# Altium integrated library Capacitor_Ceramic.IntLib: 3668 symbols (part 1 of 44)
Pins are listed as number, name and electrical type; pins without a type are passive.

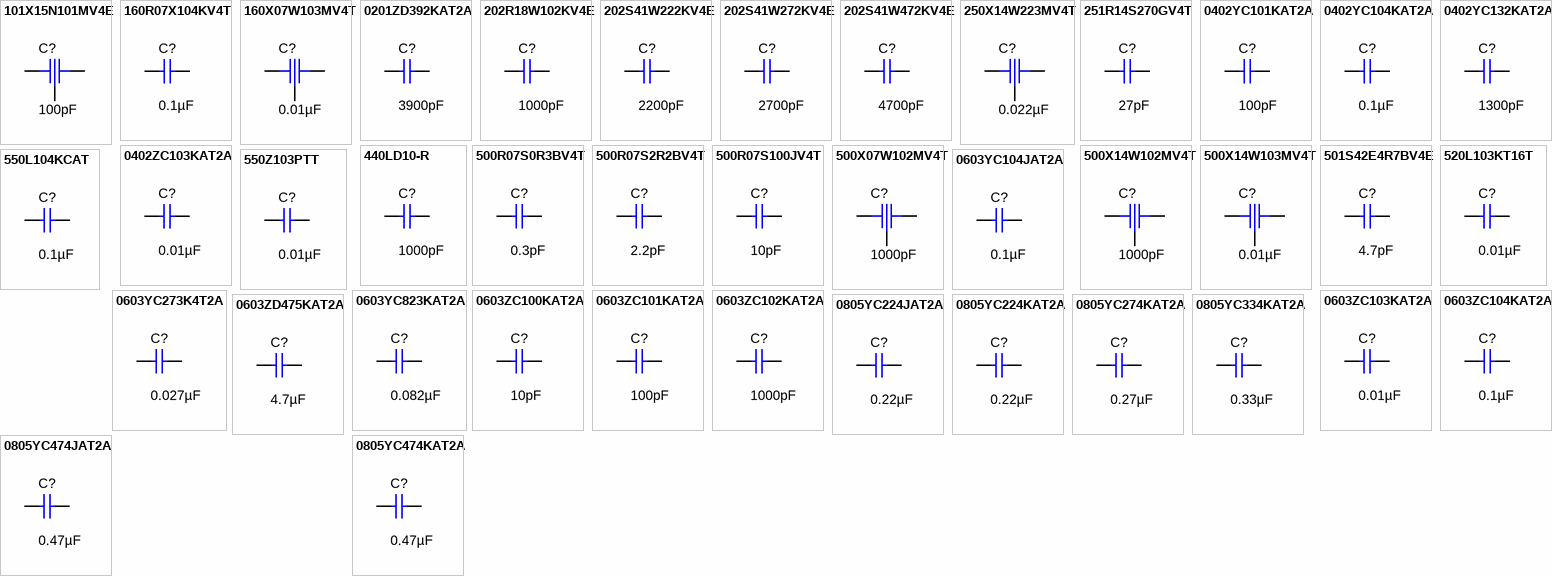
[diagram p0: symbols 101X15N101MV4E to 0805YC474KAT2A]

## 101X15N101MV4E
designator C?  ValueDisplayed: 100pF  (hidden comment: 101X15N101MV4E)
CAP, CERM, 100 pF, 100 V,+/- 20%, C0G/NP0, 0805; Manufacturer: Johanson Technology; SymbolCreator: a0411947; CompType: Capacitor; U/M: EA; Cap_F: 0.0000000001; Value: 100pF; Tolerance_%: 20; VDC_V: 100; Value2: 100V; TaMin_C: -55; TaMax_C: 125; Polarized: N; Cap_Case: 0805; SizeArea_mm2: 2.58064; SizeAreaWB_mm2: 6.88264; SizeX_mm: 2.032; SizeY_mm: 1.27; SizeZ_mm: 1.016; AEC Category: Q200; Green_Lifecycle: Not Set; Green_REACh: Incomplete
footprint X2Y_0805
pins: 1, 2, 3

## 160R07X104KV4T
designator C?  ValueDisplayed: 0.1µF  (hidden comment: 160R07X104KV4T)
CAP, CERM, 0.1 µF, 16 V,+/- 10%, X5R, 0402; Manufacturer: Johanson Technology; Polarized: N; CompType: Capacitor; Value: 0.1uF; U/M: EA; Cap_F: 0.0000001; Tolerance_%: 10; VDC_V: 16; Value2: 16V; TaMin_C: -55; TaMax_C: 85; Cap_Case: 0402; SizeArea_mm2: 0.5; SizeAreaWB_mm2: 3; SizeX_mm: 1; SizeZ_mm: 0.65; AEC Category: Q200; Green_Lifecycle: Not Set; Green_REACh: Incomplete
signal-integrity model Cap
simulation model Cap
footprint 0402_065
footprint 0402_065M
footprint 0402_065L
footprint 0402_065S
pins: 1, 2

## 160X07W103MV4T
designator C?  ValueDisplayed: 0.01µF  (hidden comment: 160X07W103MV4T)
CAP, CERM, 0.01 µF, 16 V,+/- 20%, X7R, 0402; Manufacturer: Johanson Technology; SymbolCreator: a0411947; CompType: Capacitor; U/M: EA; Cap_F: 0.00000001; Value: 0.01uF; Tolerance_%: 20; VDC_V: 16; Value2: 16V; TaMin_C: -55; TaMax_C: 125; Polarized: N; Cap_Case: 0402; SizeArea_mm2: 0.7296; SizeAreaWB_mm2: 3.5096; SizeX_mm: 1.14; SizeY_mm: 0.64; SizeZ_mm: 0.51; AEC Category: Q200
footprint X2Y_0402
pins: 1, 2, 3

## 0201ZD392KAT2A
designator C?  ValueDisplayed: 3900pF  (hidden comment: 0201ZD392KAT2A)
CAP, CERM, 3900 pF, 10 V,+/- 10%, X5R, 0201; Manufacturer: AVX; Polarized: N; CompType: Capacitor; Value: 3900pF; U/M: EA; Cap_F: 0.0000000039; Tolerance_%: 10; Value2: 10V; TaMin_C: -55; TaMax_C: 85; Cap_Case: 0201; SizeArea_mm2: 0.18; SizeAreaWB_mm2: 2.08; SizeX_mm: 0.6; SizeY_mm: 0.3; SizeZ_mm: 0.26; AEC Category: Q200; Green_Lifecycle: Active; Green_REACh: Passed
signal-integrity model Cap
simulation model Cap
footprint 0201
footprint 0201M
footprint 0201L
footprint 0201_Silk
pins: 1, 2

## 202R18W102KV4E
designator C?  ValueDisplayed: 1000pF  (hidden comment: 202R18W102KV4E)
CAP, CERM, 1000 pF, 2000 V,+/- 10%, X7R, 1206; Manufacturer: Johanson Technology; Polarized: N; CompType: Capacitor; Value: 1000pF; U/M: EA; Cap_F: 0.000000001; Tolerance_%: 10; VDC_V: 2000; Value2: 2000V; TaMin_C: -55; TaMax_C: 125; Cap_Case: 1206; SizeArea_mm2: 5.12; SizeAreaWB_mm2: 10.92; SizeX_mm: 3.2; SizeY_mm: 1.6; SizeZ_mm: 1.9; AEC Category: Q200
signal-integrity model Cap
simulation model Cap
footprint 1206_190
footprint 1206_190M
footprint 1206_190L
pins: 1, 2

## 202S41W222KV4E
designator C?  ValueDisplayed: 2200pF  (hidden comment: 202S41W222KV4E)
CAP, CERM, 2200 pF, 2000 V,+/- 10%, X7R, 1210; Manufacturer: Johanson Technology; Polarized: N; CompType: Capacitor; Value: 2200pF; U/M: EA; Cap_F: 0.0000000022; Tolerance_%: 10; VDC_V: 2000; Value2: 2000V; TaMin_C: -55; TaMax_C: 125; Cap_Case: 1210; SizeArea_mm2: 8; SizeAreaWB_mm2: 14.7; SizeX_mm: 3.2; SizeY_mm: 2.5; SizeZ_mm: 2.8; AEC Category: Q200
signal-integrity model Cap
simulation model Cap
footprint 1210_280
pins: 1, 2

## 202S41W272KV4E
designator C?  ValueDisplayed: 2700pF  (hidden comment: 202S41W272KV4E)
CAP, CERM, 2700 pF, 2000 V,+/- 10%, X7R, 1210; Manufacturer: Johanson Technology; Polarized: N; CompType: Capacitor; Value: 2700pF; U/M: EA; Cap_F: 0.0000000027; Tolerance_%: 10; VDC_V: 2000; Value2: 2000V; TaMin_C: -55; TaMax_C: 125; Cap_Case: 1210; SizeArea_mm2: 8; SizeAreaWB_mm2: 14.7; SizeX_mm: 3.2; SizeY_mm: 2.5; SizeZ_mm: 2.8; AEC Category: Q200
signal-integrity model Cap
simulation model Cap
footprint 1210_280
pins: 1, 2

## 202S41W472KV4E
designator C?  ValueDisplayed: 4700pF  (hidden comment: 202S41W472KV4E)
CAP, CERM, 4700 pF, 2000 V,+/- 10%, X7R, 1210; Manufacturer: Johanson Technology; Polarized: N; CompType: Capacitor; Value: 4700pF; U/M: EA; Cap_F: 0.0000000047; Tolerance_%: 10; VDC_V: 2000; Value2: 2000V; TaMin_C: -55; TaMax_C: 125; Cap_Case: 1210; SizeArea_mm2: 8; SizeAreaWB_mm2: 14.7; SizeX_mm: 3.2; SizeY_mm: 2.5; SizeZ_mm: 1.35; AEC Category: Q200; Green_Lifecycle: Not Set; Green_REACh: Incomplete
signal-integrity model Cap
simulation model Cap
footprint 1210
footprint 1210M
footprint 1210L
pins: 1, 2

## 250X14W223MV4T
designator C?  ValueDisplayed: 0.022µF  (hidden comment: 250X14W223MV4T)
CAP, CERM, 0.022 µF, 25 V,+/- 20%, X7R, 0603; Manufacturer: Johanson Technology; SymbolCreator: a0411947; CompType: Capacitor; U/M: EA; Cap_F: 0.000000022; Value: 0.022uF; Tolerance_%: 20; VDC_V: 25; Value2: 25V; TaMin_C: -55; TaMax_C: 125; Polarized: N; Cap_Case: 0603; SizeArea_mm2: 1.445514; SizeAreaWB_mm2: 4.960514; SizeX_mm: 1.626; SizeY_mm: 0.889; SizeZ_mm: 0.66; AEC Category: Q200; Green_Lifecycle: Active; Green_REACh: Passed
footprint X2Y_0603
pins: 1, 2, 3

## 251R14S270GV4T
designator C?  ValueDisplayed: 27pF  (hidden comment: 251R14S270GV4T)
CAP, CERM, 27 pF, 250 V,+/- 2%, C0G/NP0, 0603; Manufacturer: Johanson Technology; Polarized: N; CompType: Capacitor; Value: 27pF; U/M: EA; Cap_F: 0.000000000027; Tolerance_%: 2; VDC_V: 250; Value2: 250V; TaMin_C: -55; TaMax_C: 125; Cap_Case: 0603; SizeArea_mm2: 1.28; SizeAreaWB_mm2: 4.68; SizeX_mm: 1.6; SizeY_mm: 0.8; SizeZ_mm: 1; AEC Category: Q200
signal-integrity model Cap
simulation model Cap
footprint 0603
footprint 0603M
footprint 0603L
footprint 0603_HV
footprint 0603S
pins: 1, 2

## 0402YC101KAT2A
designator C?  ValueDisplayed: 100pF  (hidden comment: 0402YC101KAT2A)
CAP, CERM, 100 pF, 16 V,+/- 10%, X7R, 0402; Manufacturer: AVX; Polarized: N; CompType: Capacitor; Value: 100pF; U/M: EA; Cap_F: 0.0000000001; Tolerance_%: 10; VDC_V: 16; Value2: 16V; TaMin_C: -55; TaMax_C: 125; Cap_Case: 0402; SizeArea_mm2: 0.5; SizeAreaWB_mm2: 3; SizeX_mm: 1; SizeZ_mm: 0.6; AEC Category: Q200
signal-integrity model Cap
simulation model Cap
footprint 0402
footprint 0402M
footprint 0402L
footprint 0402S
pins: 1, 2

## 0402YC104KAT2A
designator C?  ValueDisplayed: 0.1µF  (hidden comment: 0402YC104KAT2A)
CAP, CERM, 0.1 µF, 16 V,+/- 10%, X7R, 0402; Manufacturer: AVX; Polarized: N; CompType: Capacitor; Value: 0.1uF; U/M: EA; Cap_F: 0.0000001; Tolerance_%: 10; VDC_V: 16; Value2: 16V; TaMin_C: -55; TaMax_C: 125; Cap_Case: 0402; SizeArea_mm2: 0.5; SizeAreaWB_mm2: 3; SizeX_mm: 1; SizeZ_mm: 0.6; AEC Category: Q200; Green_Lifecycle: Active; Green_REACh: Passed
signal-integrity model Cap
simulation model Cap
footprint 0402
footprint 0402M
footprint 0402L
footprint 0402S
pins: 1, 2

## 0402YC132KAT2A
designator C?  ValueDisplayed: 1300pF  (hidden comment: 0402YC132KAT2A)
CAP, CERM, 1300 pF, 16 V,+/- 10%, X7R, 0402; Manufacturer: AVX; Polarized: N; CompType: Capacitor; Value: 1300pF; U/M: EA; Cap_F: 0.0000000013; Tolerance_%: 10; VDC_V: 16; Value2: 16V; TaMin_C: -55; TaMax_C: 125; Cap_Case: 0402; SizeArea_mm2: 0.5; SizeAreaWB_mm2: 3; SizeX_mm: 1; SizeZ_mm: 0.6; AEC Category: Q200; Green_Lifecycle: Not Set; Green_REACh: Incomplete
signal-integrity model Cap
simulation model Cap
footprint 0402
footprint 0402M
footprint 0402L
footprint 0402S
pins: 1, 2

## 0402ZC103KAT2A
designator C?  ValueDisplayed: 0.01µF  (hidden comment: 0402ZC103KAT2A)
CAP, CERM, 0.01 µF, 10 V,+/- 10%, X7R, 0402; Manufacturer: AVX; Polarized: N; CompType: Capacitor; Value: 0.01uF; U/M: EA; Cap_F: 0.00000001; Tolerance_%: 10; Value2: 10V; TaMin_C: -55; TaMax_C: 125; Cap_Case: 0402; SizeArea_mm2: 0.5; SizeAreaWB_mm2: 3; SizeX_mm: 1; SizeZ_mm: 0.6; AEC Category: Q200
signal-integrity model Cap
simulation model Cap
footprint 0402
footprint 0402M
footprint 0402L
footprint 0402S
pins: 1, 2

## 440LD10-R
designator C?  ValueDisplayed: 1000pF  (hidden comment: 440LD10-R)
CAP, CERM, 1000 pF, X1 760 VAC/Y1 500 VAC, +/- 20%, Y5U, Disc, 9.3x12.5mm; Manufacturer: Yageo America; Polarized: N; CompType: Capacitor; Value: 1000pF; U/M: EA; Cap_F: 0.000000001; Tolerance_%: 20; TaMin_C: -30; TaMax_C: 125; Cap_Case: 440L_930x1250; SizeArea_mm2: 53.01; SizeAreaWB_mm2: 87.01; SizeX_mm: 9.3; SizeY_mm: 5.7; SizeZ_mm: 12.5; AEC Category: Q200; Green_Lifecycle: Active; Green_REACh: Passed; AC_Safety: X1Y1; VAC_X: 760; VAC_Y: 500
signal-integrity model Cap
simulation model Cap
footprint 440L_930x1250
pins: 1, 2

## 500R07S0R3BV4T
designator C?  ValueDisplayed: 0.3pF  (hidden comment: 500R07S0R3BV4T)
CAP, CERM, 0.3 pF, 50 V,+/- 30%, C0G/NP0, 0402; Manufacturer: Johanson Technology; Polarized: N; CompType: Capacitor; Value: 0.3pF; U/M: EA; Cap_F: 0.0000000000003; Tolerance_%: 30; VDC_V: 50; Value2: 50V; TaMin_C: -55; TaMax_C: 125; Cap_Case: 0402; SizeArea_mm2: 0.5; SizeAreaWB_mm2: 3; SizeX_mm: 1; SizeZ_mm: 0.6; AEC Category: Q200
signal-integrity model Cap
simulation model Cap
footprint 0402
footprint 0402M
footprint 0402L
footprint 0402S
pins: 1, 2

## 500R07S2R2BV4T
designator C?  ValueDisplayed: 2.2pF  (hidden comment: 500R07S2R2BV4T)
CAP, CERM, 2.2 pF, 50 V,+/- 5%, C0G/NP0, 0402; Manufacturer: Johanson Technology; Polarized: N; CompType: Capacitor; Value: 2.2pF; U/M: EA; Cap_F: 0.0000000000022; Tolerance_%: 5; VDC_V: 50; Value2: 50V; TaMin_C: -55; TaMax_C: 125; Cap_Case: 0402; SizeArea_mm2: 0.5; SizeAreaWB_mm2: 3; SizeX_mm: 1; SizeZ_mm: 0.6; AEC Category: Q200
signal-integrity model Cap
simulation model Cap
footprint 0402
footprint 0402M
footprint 0402L
footprint 0402S
pins: 1, 2

## 500R07S100JV4T
designator C?  ValueDisplayed: 10pF  (hidden comment: 500R07S100JV4T)
CAP, CERM, 10 pF, 50 V,+/- 5%, C0G/NP0, 0402; Manufacturer: Johanson Technology; Polarized: N; CompType: Capacitor; Value: 10pF; U/M: EA; Cap_F: 0.00000000001; Tolerance_%: 5; VDC_V: 50; Value2: 50V; TaMin_C: -55; TaMax_C: 125; Cap_Case: 0402; SizeArea_mm2: 0.5; SizeAreaWB_mm2: 3; SizeX_mm: 1; SizeZ_mm: 0.6; AEC Category: Q200; Green_Lifecycle: Active; Green_REACh: Passed
signal-integrity model Cap
simulation model Cap
footprint 0402
footprint 0402M
footprint 0402L
footprint 0402S
pins: 1, 2

## 500X07W102MV4T
designator C?  ValueDisplayed: 1000pF  (hidden comment: 500X07W102MV4T)
CAP, CERM, 1000 pF, 50 V,+/- 20%, X7R, 0402; Manufacturer: Johanson Technology; SymbolCreator: a0411947; CompType: Capacitor; U/M: EA; Cap_F: 0.000000001; Value: 1000pF; Tolerance_%: 20; VDC_V: 50; Value2: 50V; TaMin_C: -55; TaMax_C: 125; Polarized: N; Cap_Case: 0402; SizeArea_mm2: 0.7296; SizeAreaWB_mm2: 3.5096; SizeX_mm: 1.14; SizeY_mm: 0.64; SizeZ_mm: 0.51; AEC Category: Q200
footprint X2Y_0402
pins: 1, 2, 3

## 500X14W102MV4T
designator C?  ValueDisplayed: 1000pF  (hidden comment: 500X14W102MV4T)
CAP, CERM, 1000 pF, 50 V,+/- 20%, X7R, 0603; Manufacturer: Johanson Technology; SymbolCreator: a0411947; CompType: Capacitor; U/M: EA; Cap_F: 0.000000001; Value: 1000pF; Tolerance_%: 20; VDC_V: 50; Value2: 50V; TaMin_C: -55; TaMax_C: 125; Polarized: N; Cap_Case: 0603; SizeArea_mm2: 1.445514; SizeAreaWB_mm2: 4.960514; SizeX_mm: 1.626; SizeY_mm: 0.889; SizeZ_mm: 0.66; AEC Category: Q200
footprint X2Y_0603
pins: 1, 2, 3

## 500X14W103MV4T
designator C?  ValueDisplayed: 0.01µF  (hidden comment: 500X14W103MV4T)
CAP, CERM, 0.01 µF, 50 V,+/- 20%, X7R, 0603; Manufacturer: Johanson Technology; SymbolCreator: a0411947; CompType: Capacitor; U/M: EA; Cap_F: 0.00000001; Value: 0.01uF; Tolerance_%: 20; VDC_V: 50; Value2: 50V; TaMin_C: -55; TaMax_C: 125; Polarized: N; Cap_Case: 0603; SizeArea_mm2: 1.445514; SizeAreaWB_mm2: 4.960514; SizeX_mm: 1.626; SizeY_mm: 0.889; SizeZ_mm: 0.66; AEC Category: Q200
footprint X2Y_0603
pins: 1, 2, 3

## 501S42E4R7BV4E
designator C?  ValueDisplayed: 4.7pF  (hidden comment: 501S42E4R7BV4E)
CAP, CERM, 4.7 pF, 500 V,+/- 2%, C0G/NP0, 1111; Manufacturer: Johanson Technology; Polarized: N; CompType: Capacitor; Value: 4.7pF; U/M: EA; Cap_F: 0.0000000000047; Tolerance_%: 2; VDC_V: 500; Value2: 500V; TaMin_C: -55; TaMax_C: 125; Cap_Case: 1111; SizeArea_mm2: 7.7841; SizeAreaWB_mm2: 14.3641; SizeX_mm: 2.79; SizeZ_mm: 2.59; AEC Category: Q200
signal-integrity model Cap
simulation model Cap
footprint 1111
footprint 1111M
footprint 1111L
pins: 1, 2

## 520L103KT16T
designator C?  ValueDisplayed: 0.01µF  (hidden comment: 520L103KT16T)
CAP, CERM, 0.01 µF, 16 V,+/- 10%, X7R, 0402; Manufacturer: AT Ceramics; Polarized: N; CompType: Capacitor; Value: 0.01uF; U/M: EA; Cap_F: 0.00000001; Tolerance_%: 10; VDC_V: 16; Value2: 16V; TaMin_C: -55; TaMax_C: 125; Cap_Case: 0402; SizeArea_mm2: 0.5; SizeAreaWB_mm2: 3; SizeX_mm: 1; SizeZ_mm: 0.65; AEC Category: Q200; Green_Lifecycle: Not Set; Green_REACh: Incomplete
signal-integrity model Cap
simulation model Cap
footprint 0402_065
footprint 0402_065M
footprint 0402_065L
footprint 0402_065S
pins: 1, 2

## 550L104KCAT
designator C?  ValueDisplayed: 0.1µF  (hidden comment: 550L104KCAT)
CAP, CERM, 0.1 µF, 16 V,+/- 10%, 0402; Manufacturer: AT Ceramics; Polarized: N; CompType: Capacitor; Value: 0.1uF; U/M: EA; Cap_F: 0.0000001; Tolerance_%: 10; VDC_V: 16; Value2: 16V; TempCo: Unknown; TaMin_C: -55; TaMax_C: 125; Cap_Case: 0402; SizeArea_mm2: 0.5; SizeAreaWB_mm2: 3; SizeX_mm: 1; SizeZ_mm: 0.65; AEC Category: Q200; Green_Lifecycle: Not Set; Green_REACh: Incomplete
signal-integrity model Cap
simulation model Cap
footprint 0402_065
footprint 0402_065M
footprint 0402_065L
footprint 0402_065S
pins: 1, 2

## 550Z103PTT
designator C?  ValueDisplayed: 0.01µF  (hidden comment: 550Z103PTT)
CAP, CERM, 0.01 µF, 6.3 V,+100/-0%, C0G/NP0, 0201; Manufacturer: AT Ceramics; Polarized: N; CompType: Capacitor; Value: 0.01uF; U/M: EA; Cap_F: 0.00000001; Tolerance_%: 100; VDC_V: 6.3; Value2: 6.3V; TaMin_C: -55; TaMax_C: 125; Cap_Case: 0201; SizeArea_mm2: 0.18; SizeAreaWB_mm2: 2.08; SizeX_mm: 0.6; SizeY_mm: 0.3; SizeZ_mm: 0.33; AEC Category: Q200; Green_Lifecycle: Not Set; Green_REACh: Incomplete
signal-integrity model Cap
simulation model Cap
footprint 0201_033
footprint 0201_033M
footprint 0201_033L
pins: 1, 2

## 0603YC104JAT2A
designator C?  ValueDisplayed: 0.1µF  (hidden comment: 0603YC104JAT2A)
CAP, CERM, 0.1 µF, 16 V,+/- 5%, X7R, 0603; Manufacturer: AVX; Polarized: N; CompType: Capacitor; Value: 0.1uF; U/M: EA; Cap_F: 0.0000001; Tolerance_%: 5; ESR_ohm: 0.039; Value1: 0.039 ohm; VDC_V: 16; Value2: 16V; TaMin_C: -55; TaMax_C: 125; Cap_Case: 0603; SizeArea_mm2: 1.28; SizeAreaWB_mm2: 4.68; SizeX_mm: 1.6; SizeY_mm: 0.8; SizeZ_mm: 1; AEC Category: Q200; Green_Lifecycle: Active; Green_REACh: Passed
signal-integrity model Cap
simulation model Cap
footprint 0603
footprint 0603M
footprint 0603L
footprint 0603_HV
footprint 0603S
pins: 1, 2

## 0603YC273K4T2A
designator C?  ValueDisplayed: 0.027µF  (hidden comment: 0603YC273K4T2A)
CAP, CERM, 0.027 µF, 16 V,+/- 10%, X7R, AEC-Q200 Grade 1, 0603; Manufacturer: AVX; Polarized: N; CompType: Capacitor; Value: 0.027uF; U/M: EA; Cap_F: 0.000000027; Tolerance_%: 10; VDC_V: 16; Value2: 16V; TaMin_C: -55; TaMax_C: 125; Cap_Case: 0603; SizeArea_mm2: 1.28; SizeAreaWB_mm2: 4.68; SizeX_mm: 1.6; SizeY_mm: 0.8; SizeZ_mm: 1; AEC Category: Q200; AEC Qualified: Y; Green_Lifecycle: Not Set; Green_REACh: Incomplete
signal-integrity model Cap
simulation model Cap
footprint 0603
footprint 0603M
footprint 0603L
footprint 0603_HV
footprint 0603S
pins: 1, 2

## 0603YC823KAT2A
designator C?  ValueDisplayed: 0.082µF  (hidden comment: 0603YC823KAT2A)
CAP, CERM, 0.082 µF, 16 V,+/- 10%, X7R, 0603; Manufacturer: AVX; Polarized: N; CompType: Capacitor; Value: 0.082uF; U/M: EA; Cap_F: 0.000000082; Tolerance_%: 10; ESR_ohm: 0.042; Value1: 0.042 ohm; VDC_V: 16; Value2: 16V; TaMin_C: -55; TaMax_C: 125; Cap_Case: 0603; SizeArea_mm2: 1.28; SizeAreaWB_mm2: 4.68; SizeX_mm: 1.6; SizeY_mm: 0.8; SizeZ_mm: 1; AEC Category: Q200; Green_Lifecycle: Not Set; Green_REACh: Incomplete
signal-integrity model Cap
simulation model Cap
footprint 0603
footprint 0603M
footprint 0603L
footprint 0603_HV
footprint 0603S
pins: 1, 2

## 0603ZC100KAT2A
designator C?  ValueDisplayed: 10pF  (hidden comment: 0603ZC100KAT2A)
CAP, CERM, 10 pF, 10 V,+/- 10%, X7R, 0603; Manufacturer: AVX; Polarized: N; CompType: Capacitor; Value: 10pF; U/M: EA; Cap_F: 0.00000000001; Tolerance_%: 10; Value2: 10V; TaMin_C: -55; TaMax_C: 125; Cap_Case: 0603; SizeArea_mm2: 1.28; SizeAreaWB_mm2: 4.68; SizeX_mm: 1.6; SizeY_mm: 0.8; SizeZ_mm: 1; AEC Category: Q200
signal-integrity model Cap
simulation model Cap
footprint 0603
footprint 0603M
footprint 0603L
footprint 0603_HV
footprint 0603S
pins: 1, 2

## 0603ZC101KAT2A
designator C?  ValueDisplayed: 100pF  (hidden comment: 0603ZC101KAT2A)
CAP, CERM, 100 pF, 10 V,+/- 10%, X7R, 0603; Manufacturer: AVX; Polarized: N; CompType: Capacitor; Value: 100pF; U/M: EA; Cap_F: 0.0000000001; Tolerance_%: 10; Value2: 10V; TaMin_C: -55; TaMax_C: 125; Cap_Case: 0603; SizeArea_mm2: 1.28; SizeAreaWB_mm2: 4.68; SizeX_mm: 1.6; SizeY_mm: 0.8; SizeZ_mm: 1; AEC Category: Q200
signal-integrity model Cap
simulation model Cap
footprint 0603
footprint 0603M
footprint 0603L
footprint 0603_HV
footprint 0603S
pins: 1, 2

## 0603ZC102KAT2A
designator C?  ValueDisplayed: 1000pF  (hidden comment: 0603ZC102KAT2A)
CAP, CERM, 1000 pF, 10 V,+/- 10%, X7R, 0603; Manufacturer: AVX; Polarized: N; CompType: Capacitor; Value: 1000pF; U/M: EA; Cap_F: 0.000000001; Tolerance_%: 10; Value2: 10V; TaMin_C: -55; TaMax_C: 125; Cap_Case: 0603; SizeArea_mm2: 1.28; SizeAreaWB_mm2: 4.68; SizeX_mm: 1.6; SizeY_mm: 0.8; SizeZ_mm: 1; AEC Category: Q200
signal-integrity model Cap
simulation model Cap
footprint 0603
footprint 0603M
footprint 0603L
footprint 0603_HV
footprint 0603S
pins: 1, 2

## 0603ZC103KAT2A
designator C?  ValueDisplayed: 0.01µF  (hidden comment: 0603ZC103KAT2A)
CAP, CERM, 0.01 µF, 10 V,+/- 10%, X7R, 0603; Manufacturer: AVX; Polarized: N; CompType: Capacitor; Value: 0.01uF; U/M: EA; Cap_F: 0.00000001; Tolerance_%: 10; Value2: 10V; TaMin_C: -55; TaMax_C: 125; Cap_Case: 0603; SizeArea_mm2: 1.28; SizeAreaWB_mm2: 4.68; SizeX_mm: 1.6; SizeY_mm: 0.8; SizeZ_mm: 1; AEC Category: Q200; Green_Lifecycle: Active; Green_REACh: Passed
signal-integrity model Cap
simulation model Cap
footprint 0603
footprint 0603M
footprint 0603L
footprint 0603_HV
footprint 0603S
pins: 1, 2

## 0603ZC104KAT2A
designator C?  ValueDisplayed: 0.1µF  (hidden comment: 0603ZC104KAT2A)
CAP, CERM, 0.1 µF, 10 V,+/- 10%, X7R, 0603; Manufacturer: AVX; Polarized: N; CompType: Capacitor; Value: 0.1uF; U/M: EA; Cap_F: 0.0000001; Tolerance_%: 10; Value2: 10V; TaMin_C: -55; TaMax_C: 125; Cap_Case: 0603; SizeArea_mm2: 1.28; SizeAreaWB_mm2: 4.68; SizeX_mm: 1.6; SizeY_mm: 0.8; SizeZ_mm: 1; AEC Category: Q200
signal-integrity model Cap
simulation model Cap
footprint 0603
footprint 0603M
footprint 0603L
footprint 0603_HV
footprint 0603S
pins: 1, 2

## 0603ZD475KAT2A
designator C?  ValueDisplayed: 4.7µF  (hidden comment: 0603ZD475KAT2A)
CAP, CERM, 4.7 µF, 10 V,+/- 10%, X5R, 0603; Manufacturer: AVX; Polarized: N; CompType: Capacitor; Value: 4.7uF; U/M: EA; Cap_F: 0.0000047; Tolerance_%: 10; Value2: 10V; TaMin_C: -55; TaMax_C: 85; Cap_Case: 0603; SizeArea_mm2: 1.28; SizeAreaWB_mm2: 4.68; SizeX_mm: 1.6; SizeY_mm: 0.8; SizeZ_mm: 1; AEC Category: Q200; Green_Lifecycle: Active; Green_REACh: Passed
signal-integrity model Cap
simulation model Cap
footprint 0603
footprint 0603M
footprint 0603L
footprint 0603_HV
footprint 0603S
pins: 1, 2

## 0805YC224JAT2A
designator C?  ValueDisplayed: 0.22µF  (hidden comment: 0805YC224JAT2A)
CAP, CERM, 0.22 µF, 16 V,+/- 5%, X7R, 0805; Manufacturer: AVX; Polarized: N; CompType: Capacitor; Value: 0.22uF; U/M: EA; Cap_F: 0.00000022; Tolerance_%: 5; ESR_ohm: 0.016; Value1: 0.016 ohm; VDC_V: 16; Value2: 16V; TaMin_C: -55; TaMax_C: 125; Cap_Case: 0805; SizeArea_mm2: 2.5; SizeAreaWB_mm2: 6.75; SizeX_mm: 2; SizeY_mm: 1.25; SizeZ_mm: 1.45; AEC Category: Q200; Green_Lifecycle: Not Set; Green_REACh: Incomplete
signal-integrity model Cap
simulation model Cap
footprint 0805_HV
footprint 0805_HV1
footprint 0805
footprint 0805M
footprint 0805L
pins: 1, 2

## 0805YC224KAT2A
designator C?  ValueDisplayed: 0.22µF  (hidden comment: 0805YC224KAT2A)
CAP, CERM, 0.22 µF, 16 V,+/- 10%, X7R, 0805; Manufacturer: AVX; Polarized: N; CompType: Capacitor; Value: 0.22uF; U/M: EA; Cap_F: 0.00000022; Tolerance_%: 10; ESR_ohm: 0.016; Value1: 0.016 ohm; VDC_V: 16; Value2: 16V; TaMin_C: -55; TaMax_C: 125; Cap_Case: 0805; SizeArea_mm2: 2.5; SizeAreaWB_mm2: 6.75; SizeX_mm: 2; SizeY_mm: 1.25; SizeZ_mm: 1.45; AEC Category: Q200; Green_Lifecycle: Not Set; Green_REACh: Incomplete
signal-integrity model Cap
simulation model Cap
footprint 0805_HV
footprint 0805_HV1
footprint 0805
footprint 0805M
footprint 0805L
pins: 1, 2

## 0805YC274KAT2A
designator C?  ValueDisplayed: 0.27µF  (hidden comment: 0805YC274KAT2A)
CAP, CERM, 0.27 µF, 16 V,+/- 10%, X7R, 0805; Manufacturer: AVX; Polarized: N; CompType: Capacitor; Value: 0.27uF; U/M: EA; Cap_F: 0.00000027; Tolerance_%: 10; ESR_ohm: 0.015; Value1: 0.015 ohm; VDC_V: 16; Value2: 16V; TaMin_C: -55; TaMax_C: 125; Cap_Case: 0805; SizeArea_mm2: 2.5; SizeAreaWB_mm2: 6.75; SizeX_mm: 2; SizeY_mm: 1.25; SizeZ_mm: 1.45; AEC Category: Q200; Green_Lifecycle: Not Set; Green_REACh: Incomplete
signal-integrity model Cap
simulation model Cap
footprint 0805_HV
footprint 0805_HV1
footprint 0805
footprint 0805M
footprint 0805L
pins: 1, 2

## 0805YC334KAT2A
designator C?  ValueDisplayed: 0.33µF  (hidden comment: 0805YC334KAT2A)
CAP, CERM, 0.33 µF, 16 V,+/- 10%, X7R, 0805; Manufacturer: AVX; Polarized: N; CompType: Capacitor; Value: 0.33uF; U/M: EA; Cap_F: 0.00000033; Tolerance_%: 10; ESR_ohm: 0.013; Value1: 0.013 ohm; VDC_V: 16; Value2: 16V; TaMin_C: -55; TaMax_C: 125; Cap_Case: 0805; SizeArea_mm2: 2.5; SizeAreaWB_mm2: 6.75; SizeX_mm: 2; SizeY_mm: 1.25; SizeZ_mm: 1.45; AEC Category: Q200; Green_Lifecycle: Active; Green_REACh: Passed
signal-integrity model Cap
simulation model Cap
footprint 0805_HV
footprint 0805_HV1
footprint 0805
footprint 0805M
footprint 0805L
pins: 1, 2

## 0805YC474JAT2A
designator C?  ValueDisplayed: 0.47µF  (hidden comment: 0805YC474JAT2A)
CAP, CERM, 0.47 µF, 16 V,+/- 5%, X7R, 0805; Manufacturer: AVX; Polarized: N; CompType: Capacitor; Value: 0.47uF; U/M: EA; Cap_F: 0.00000047; Tolerance_%: 5; ESR_ohm: 0.011; Value1: 0.011 ohm; VDC_V: 16; Value2: 16V; TaMin_C: -55; TaMax_C: 125; Cap_Case: 0805; SizeArea_mm2: 2.5; SizeAreaWB_mm2: 6.75; SizeX_mm: 2; SizeY_mm: 1.25; SizeZ_mm: 1.45; AEC Category: Q200; Green_Lifecycle: Active; Green_REACh: Passed
signal-integrity model Cap
simulation model Cap
footprint 0805_HV
footprint 0805_HV1
footprint 0805
footprint 0805M
footprint 0805L
pins: 1, 2

## 0805YC474KAT2A
designator C?  ValueDisplayed: 0.47µF  (hidden comment: 0805YC474KAT2A)
CAP, CERM, 0.47 µF, 16 V,+/- 10%, X7R, 0805; Manufacturer: AVX; Polarized: N; CompType: Capacitor; Value: 0.47uF; U/M: EA; Cap_F: 0.00000047; Tolerance_%: 10; ESR_ohm: 0.011; Value1: 0.011 ohm; VDC_V: 16; Value2: 16V; TaMin_C: -55; TaMax_C: 125; Cap_Case: 0805; SizeArea_mm2: 2.5; SizeAreaWB_mm2: 6.75; SizeX_mm: 2; SizeY_mm: 1.25; SizeZ_mm: 1.45; AEC Category: Q200; Green_Lifecycle: Active; Green_REACh: Passed
signal-integrity model Cap
simulation model Cap
footprint 0805_HV
footprint 0805_HV1
footprint 0805
footprint 0805M
footprint 0805L
pins: 1, 2

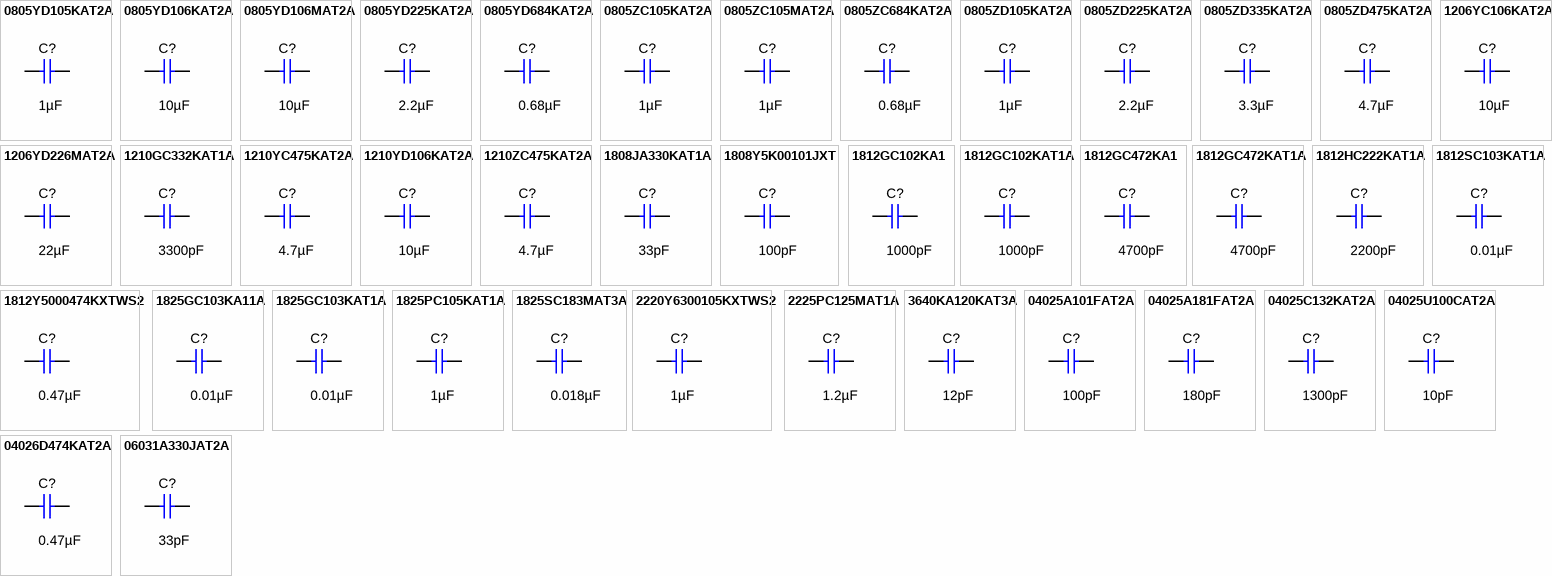
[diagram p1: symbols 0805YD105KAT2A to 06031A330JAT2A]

## 0805YD105KAT2A
designator C?  ValueDisplayed: 1µF  (hidden comment: 0805YD105KAT2A)
CAP, CERM, 1 µF, 16 V,+/- 10%, X5R, 0805; Manufacturer: AVX; Polarized: N; CompType: Capacitor; Value: 1uF; U/M: EA; Cap_F: 0.000001; Tolerance_%: 10; ESR_ohm: 0.012; Value1: 0.012 ohm; VDC_V: 16; Value2: 16V; TaMin_C: -55; TaMax_C: 85; Cap_Case: 0805; SizeArea_mm2: 2.5; SizeAreaWB_mm2: 6.75; SizeX_mm: 2; SizeY_mm: 1.25; SizeZ_mm: 1.45; AEC Category: Q200; Green_Lifecycle: Active; Green_REACh: Passed
signal-integrity model Cap
simulation model Cap
footprint 0805_HV
footprint 0805_HV1
footprint 0805
footprint 0805M
footprint 0805L
pins: 1, 2

## 0805YD106KAT2A
designator C?  ValueDisplayed: 10µF  (hidden comment: 0805YD106KAT2A)
CAP, CERM, 10 µF, 16 V,+/- 10%, X5R, 0805; Manufacturer: AVX; Polarized: N; CompType: Capacitor; Value: 10uF; U/M: EA; Cap_F: 0.00001; Tolerance_%: 10; VDC_V: 16; Value2: 16V; TaMin_C: -55; TaMax_C: 85; Cap_Case: 0805; SizeArea_mm2: 2.5; SizeAreaWB_mm2: 6.75; SizeX_mm: 2; SizeY_mm: 1.25; SizeZ_mm: 1.45; AEC Category: Q200; Green_Lifecycle: Active; Green_REACh: Passed
signal-integrity model Cap
simulation model Cap
footprint 0805_HV
footprint 0805_HV1
footprint 0805
footprint 0805M
footprint 0805L
pins: 1, 2

## 0805YD106MAT2A
designator C?  ValueDisplayed: 10µF  (hidden comment: 0805YD106MAT2A)
CAP, CERM, 10 µF, 16 V,+/- 20%, X5R, 0805; Manufacturer: AVX; Polarized: N; CompType: Capacitor; Value: 10uF; U/M: EA; Cap_F: 0.00001; Tolerance_%: 20; VDC_V: 16; Value2: 16V; TaMin_C: -55; TaMax_C: 85; Cap_Case: 0805; SizeArea_mm2: 2.5; SizeAreaWB_mm2: 6.75; SizeX_mm: 2; SizeY_mm: 1.25; SizeZ_mm: 1.45; AEC Category: Q200; Green_Lifecycle: Active; Green_REACh: Passed
signal-integrity model Cap
simulation model Cap
footprint 0805_HV
footprint 0805_HV1
footprint 0805
footprint 0805M
footprint 0805L
pins: 1, 2

## 0805YD225KAT2A
designator C?  ValueDisplayed: 2.2µF  (hidden comment: 0805YD225KAT2A)
CAP, CERM, 2.2 µF, 16 V,+/- 10%, X5R, 0805; Manufacturer: AVX; Polarized: N; CompType: Capacitor; Value: 2.2uF; U/M: EA; Cap_F: 0.0000022; Tolerance_%: 10; ESR_ohm: 0.009; Value1: 0.009 ohm; VDC_V: 16; Value2: 16V; TaMin_C: -55; TaMax_C: 85; Cap_Case: 0805; SizeArea_mm2: 2.5; SizeAreaWB_mm2: 6.75; SizeX_mm: 2; SizeY_mm: 1.25; SizeZ_mm: 1.45; AEC Category: Q200; Green_Lifecycle: Active; Green_REACh: Passed
signal-integrity model Cap
simulation model Cap
footprint 0805_HV
footprint 0805_HV1
footprint 0805
footprint 0805M
footprint 0805L
pins: 1, 2

## 0805YD684KAT2A
designator C?  ValueDisplayed: 0.68µF  (hidden comment: 0805YD684KAT2A)
CAP, CERM, 0.68 µF, 16 V,+/- 10%, X5R, 0805; Manufacturer: AVX; Polarized: N; CompType: Capacitor; Value: 0.68uF; U/M: EA; Cap_F: 0.00000068; Tolerance_%: 10; ESR_ohm: 0.015; Value1: 0.015 ohm; VDC_V: 16; Value2: 16V; TaMin_C: -55; TaMax_C: 85; Cap_Case: 0805; SizeArea_mm2: 2.5; SizeAreaWB_mm2: 6.75; SizeX_mm: 2; SizeY_mm: 1.25; SizeZ_mm: 1.45; AEC Category: Q200; Green_Lifecycle: Not Set; Green_REACh: Incomplete
signal-integrity model Cap
simulation model Cap
footprint 0805_HV
footprint 0805_HV1
footprint 0805
footprint 0805M
footprint 0805L
pins: 1, 2

## 0805ZC105KAT2A
designator C?  ValueDisplayed: 1µF  (hidden comment: 0805ZC105KAT2A)
CAP, CERM, 1 µF, 10 V,+/- 10%, X7R, 0805; Manufacturer: AVX; Polarized: N; CompType: Capacitor; Value: 1uF; U/M: EA; Cap_F: 0.000001; Tolerance_%: 10; ESR_ohm: 0.008; Value1: 0.008 ohm; Value2: 10V; TaMin_C: -55; TaMax_C: 125; Cap_Case: 0805; SizeArea_mm2: 2.5; SizeAreaWB_mm2: 6.75; SizeX_mm: 2; SizeY_mm: 1.25; SizeZ_mm: 1.45; AEC Category: Q200; Green_Lifecycle: Not Set; Green_REACh: Incomplete
signal-integrity model Cap
simulation model Cap
footprint 0805_HV
footprint 0805_HV1
footprint 0805
footprint 0805M
footprint 0805L
pins: 1, 2

## 0805ZC105MAT2A
designator C?  ValueDisplayed: 1µF  (hidden comment: 0805ZC105MAT2A)
CAP, CERM, 1 µF, 10 V,+/- 20%, X7R, 0805; Manufacturer: AVX; Polarized: N; CompType: Capacitor; Value: 1uF; U/M: EA; Cap_F: 0.000001; Tolerance_%: 20; ESR_ohm: 0.008; Value1: 0.008 ohm; VDC_V: 10; Value2: 10V; TaMin_C: -55; TaMax_C: 125; Cap_Case: 0805; SizeArea_mm2: 2.5; SizeAreaWB_mm2: 6.75; SizeX_mm: 2; SizeY_mm: 1.25; SizeZ_mm: 1.45; AEC Category: Q200; Green_Lifecycle: Not Set; Green_REACh: Incomplete
signal-integrity model Cap
simulation model Cap
footprint 0805_HV
footprint 0805_HV1
footprint 0805
footprint 0805M
footprint 0805L
pins: 1, 2

## 0805ZC684KAT2A
designator C?  ValueDisplayed: 0.68µF  (hidden comment: 0805ZC684KAT2A)
CAP, CERM, 0.68 µF, 10 V,+/- 10%, X7R, 0805; Manufacturer: AVX; Polarized: N; CompType: Capacitor; Value: 0.68uF; U/M: EA; Cap_F: 0.00000068; Tolerance_%: 10; ESR_ohm: 0.01; Value1: 0.01 ohm; Value2: 10V; TaMin_C: -55; TaMax_C: 125; Cap_Case: 0805; SizeArea_mm2: 2.5; SizeAreaWB_mm2: 6.75; SizeX_mm: 2; SizeY_mm: 1.25; SizeZ_mm: 1.45; AEC Category: Q200; Green_Lifecycle: Not Set; Green_REACh: Incomplete
signal-integrity model Cap
simulation model Cap
footprint 0805_HV
footprint 0805_HV1
footprint 0805
footprint 0805M
footprint 0805L
pins: 1, 2

## 0805ZD105KAT2A
designator C?  ValueDisplayed: 1µF  (hidden comment: 0805ZD105KAT2A)
CAP, CERM, 1 µF, 10 V,+/- 10%, X5R, 0805; Manufacturer: AVX; Polarized: N; CompType: Capacitor; Value: 1uF; U/M: EA; Cap_F: 0.000001; Tolerance_%: 10; ESR_ohm: 0.012; Value1: 0.012 ohm; Value2: 10V; TaMin_C: -55; TaMax_C: 85; Cap_Case: 0805; SizeArea_mm2: 2.5; SizeAreaWB_mm2: 6.75; SizeX_mm: 2; SizeY_mm: 1.25; SizeZ_mm: 1.45; AEC Category: Q200; Green_Lifecycle: Active; Green_REACh: Passed
signal-integrity model Cap
simulation model Cap
footprint 0805_HV
footprint 0805_HV1
footprint 0805
footprint 0805M
footprint 0805L
pins: 1, 2

## 0805ZD225KAT2A
designator C?  ValueDisplayed: 2.2µF  (hidden comment: 0805ZD225KAT2A)
CAP, CERM, 2.2 µF, 10 V,+/- 10%, X5R, 0805; Manufacturer: AVX; Polarized: N; CompType: Capacitor; Value: 2.2uF; U/M: EA; Cap_F: 0.0000022; Tolerance_%: 10; ESR_ohm: 0.009; Value1: 0.009 ohm; Value2: 10V; TaMin_C: -55; TaMax_C: 85; Cap_Case: 0805; SizeArea_mm2: 2.5; SizeAreaWB_mm2: 6.75; SizeX_mm: 2; SizeY_mm: 1.25; SizeZ_mm: 1.45; AEC Category: Q200; Green_Lifecycle: Active; Green_REACh: Passed
signal-integrity model Cap
simulation model Cap
footprint 0805_HV
footprint 0805_HV1
footprint 0805
footprint 0805M
footprint 0805L
pins: 1, 2

## 0805ZD335KAT2A
designator C?  ValueDisplayed: 3.3µF  (hidden comment: 0805ZD335KAT2A)
CAP, CERM, 3.3 µF, 10 V,+/- 10%, X5R, 0805; Manufacturer: AVX; Polarized: N; CompType: Capacitor; Value: 3.3uF; U/M: EA; Cap_F: 0.0000033; Tolerance_%: 10; ESR_ohm: 0.008; Value1: 0.008 ohm; Value2: 10V; TaMin_C: -55; TaMax_C: 85; Cap_Case: 0805; SizeArea_mm2: 2.5; SizeAreaWB_mm2: 6.75; SizeX_mm: 2; SizeY_mm: 1.25; SizeZ_mm: 1.45; AEC Category: Q200; Green_Lifecycle: Not Set; Green_REACh: Incomplete
signal-integrity model Cap
simulation model Cap
footprint 0805_HV
footprint 0805_HV1
footprint 0805
footprint 0805M
footprint 0805L
pins: 1, 2

## 0805ZD475KAT2A
designator C?  ValueDisplayed: 4.7µF  (hidden comment: 0805ZD475KAT2A)
CAP, CERM, 4.7 µF, 10 V,+/- 10%, X5R, 0805; Manufacturer: AVX; Polarized: N; CompType: Capacitor; Value: 4.7uF; U/M: EA; Cap_F: 0.0000047; Tolerance_%: 10; ESR_ohm: 0.007; Value1: 0.007 ohm; Value2: 10V; TaMin_C: -55; TaMax_C: 85; Cap_Case: 0805; SizeArea_mm2: 2.5; SizeAreaWB_mm2: 6.75; SizeX_mm: 2; SizeY_mm: 1.25; SizeZ_mm: 1.45; AEC Category: Q200; Green_Lifecycle: Active; Green_REACh: Passed
signal-integrity model Cap
simulation model Cap
footprint 0805_HV
footprint 0805_HV1
footprint 0805
footprint 0805M
footprint 0805L
pins: 1, 2

## 1206YC106KAT2A
designator C?  ValueDisplayed: 10µF  (hidden comment: 1206YC106KAT2A)
CAP, CERM, 10 µF, 16 V,+/- 10%, X7R, 1206; Manufacturer: AVX; Polarized: N; CompType: Capacitor; Value: 10uF; U/M: EA; Cap_F: 0.00001; Tolerance_%: 10; VDC_V: 16; Value2: 16V; TaMin_C: -55; TaMax_C: 125; Cap_Case: 1206; SizeArea_mm2: 5.12; SizeAreaWB_mm2: 10.92; SizeX_mm: 3.2; SizeY_mm: 1.6; SizeZ_mm: 1.9; AEC Category: Q200; Green_Lifecycle: Active; Green_REACh: Passed
signal-integrity model Cap
simulation model Cap
footprint 1206_190
footprint 1206_190M
footprint 1206_190L
pins: 1, 2

## 1206YD226MAT2A
designator C?  ValueDisplayed: 22µF  (hidden comment: 1206YD226MAT2A)
CAP, CERM, 22 µF, 16 V,+/- 20%, X5R, 1206; Manufacturer: AVX; Polarized: N; CompType: Capacitor; Value: 22uF; U/M: EA; Cap_F: 0.000022; Tolerance_%: 20; VDC_V: 16; Value2: 16V; TaMin_C: -55; TaMax_C: 85; Cap_Case: 1206; SizeArea_mm2: 5.12; SizeAreaWB_mm2: 10.92; SizeX_mm: 3.2; SizeY_mm: 1.6; SizeZ_mm: 1.9; AEC Category: Q200; Green_Lifecycle: Active; Green_REACh: Passed
signal-integrity model Cap
simulation model Cap
footprint 1206_190
footprint 1206_190M
footprint 1206_190L
pins: 1, 2

## 1210GC332KAT1A
designator C?  ValueDisplayed: 3300pF  (hidden comment: 1210GC332KAT1A)
CAP, CERM, 3300 pF, 2000 V,+/- 10%, X7R, 1210; Manufacturer: AVX; Polarized: N; CompType: Capacitor; Value: 3300pF; U/M: EA; Cap_F: 0.0000000033; Tolerance_%: 10; VDC_V: 2000; Value2: 2000V; TaMin_C: -55; TaMax_C: 125; Cap_Case: 1210; SizeArea_mm2: 8; SizeAreaWB_mm2: 14.7; SizeX_mm: 3.2; SizeY_mm: 2.5; SizeZ_mm: 1.7; AEC Category: Q200
signal-integrity model Cap
simulation model Cap
footprint 1210_170
pins: 1, 2

## 1210YC475KAT2A
designator C?  ValueDisplayed: 4.7µF  (hidden comment: 1210YC475KAT2A)
CAP, CERM, 4.7 µF, 16 V,+/- 10%, X7R, 1210; Manufacturer: AVX; Polarized: N; CompType: Capacitor; Value: 4.7uF; U/M: EA; Cap_F: 0.0000047; Tolerance_%: 10; VDC_V: 16; Value2: 16V; TaMin_C: -55; TaMax_C: 125; Cap_Case: 1210; SizeArea_mm2: 8; SizeAreaWB_mm2: 14.7; SizeX_mm: 3.2; SizeY_mm: 2.5; SizeZ_mm: 2.3; AEC Category: Q200
signal-integrity model Cap
simulation model Cap
footprint 1210_230
footprint 1210_230M
footprint 1210_230L
pins: 1, 2

## 1210YD106KAT2A
designator C?  ValueDisplayed: 10µF  (hidden comment: 1210YD106KAT2A)
CAP, CERM, 10 µF, 16 V,+/- 10%, X5R, 1210; Manufacturer: AVX; Polarized: N; CompType: Capacitor; Value: 10uF; U/M: EA; Cap_F: 0.00001; Tolerance_%: 10; VDC_V: 16; Value2: 16V; TaMin_C: -55; TaMax_C: 85; Cap_Case: 1210; SizeArea_mm2: 8; SizeAreaWB_mm2: 14.7; SizeX_mm: 3.2; SizeY_mm: 2.5; SizeZ_mm: 2.8; AEC Category: Q200; Green_Lifecycle: Active; Green_REACh: Passed
signal-integrity model Cap
simulation model Cap
footprint 1210_280
pins: 1, 2

## 1210ZC475KAT2A
designator C?  ValueDisplayed: 4.7µF  (hidden comment: 1210ZC475KAT2A)
CAP, CERM, 4.7 µF, 10 V,+/- 10%, X7R, 1210; Manufacturer: AVX; Polarized: N; CompType: Capacitor; Value: 4.7uF; U/M: EA; Cap_F: 0.0000047; Tolerance_%: 10; Value2: 10V; TaMin_C: -55; TaMax_C: 125; Cap_Case: 1210; SizeArea_mm2: 8; SizeAreaWB_mm2: 14.7; SizeX_mm: 3.2; SizeY_mm: 2.5; SizeZ_mm: 2.8; AEC Category: Q200; Green_Lifecycle: Active; Green_REACh: Passed
signal-integrity model Cap
simulation model Cap
footprint 1210_280
pins: 1, 2

## 1808JA330KAT1A
designator C?  ValueDisplayed: 33pF  (hidden comment: 1808JA330KAT1A)
CAP, CERM, 33 pF, 4000 V,+/- 10%, C0G/NP0, 1808; Manufacturer: AVX; Polarized: N; CompType: Capacitor; Value: 33pF; U/M: EA; Cap_F: 0.000000000033; Tolerance_%: 10; VDC_V: 4000; Value2: 4000V; TaMin_C: -55; TaMax_C: 125; Cap_Case: 1808; SizeArea_mm2: 9; SizeAreaWB_mm2: 16.5; SizeX_mm: 4.5; SizeY_mm: 2; SizeZ_mm: 2.03; AEC Category: Q200
signal-integrity model Cap
simulation model Cap
footprint 1808
footprint 1808_M
footprint 1808_L
pins: 1, 2

## 1808Y5K00101JXT
designator C?  ValueDisplayed: 100pF  (hidden comment: 1808Y5K00101JXT)
CAP, CERM, 100 pF, 5000 V,+/- 5%, X7R, 1808; Manufacturer: Knowles Capacitors; Polarized: N; CompType: Capacitor; Value: 100pF; U/M: EA; Cap_F: 0.0000000001; Tolerance_%: 5; VDC_V: 5000; Value2: 5000V; TaMin_C: -55; TaMax_C: 125; Cap_Case: 1808; SizeArea_mm2: 9; SizeAreaWB_mm2: 16.5; SizeX_mm: 4.5; SizeY_mm: 2; SizeZ_mm: 2.03; AEC Category: Q200; Green_Lifecycle: Not Set; Green_REACh: Incomplete
signal-integrity model Cap
simulation model Cap
footprint 1808
footprint 1808_M
footprint 1808_L
pins: 1, 2

## 1812GC102KA1
designator C?  ValueDisplayed: 1000pF  (hidden comment: 1812GC102KA1)
CAP, CERM, 1000 pF, 2000 V,+/- 10%, X7R, 1812; Manufacturer: AVX; Polarized: N; CompType: Capacitor; Value: 1000pF; U/M: EA; Cap_F: 0.000000001; Tolerance_%: 10; VDC_V: 2000; Value2: 2000V; TaMin_C: -55; TaMax_C: 125; Cap_Case: 1812; SizeArea_mm2: 14.4; SizeAreaWB_mm2: 23.1; SizeX_mm: 4.5; SizeY_mm: 3.2; SizeZ_mm: 2.54; AEC Category: Q200; Green_Lifecycle: Not Set; Green_REACh: Incomplete
signal-integrity model Cap
simulation model Cap
footprint 1812_254
pins: 1, 2

## 1812GC102KAT1A
designator C?  ValueDisplayed: 1000pF  (hidden comment: 1812GC102KAT1A)
CAP, CERM, 1000 pF, 2000 V,+/- 10%, X7R, 1812; Manufacturer: AVX; Polarized: N; CompType: Capacitor; Value: 1000pF; U/M: EA; Cap_F: 0.000000001; Tolerance_%: 10; VDC_V: 2000; Value2: 2000V; TaMin_C: -55; TaMax_C: 125; Cap_Case: 1812; SizeArea_mm2: 14.4; SizeAreaWB_mm2: 23.1; SizeX_mm: 4.5; SizeY_mm: 3.2; SizeZ_mm: 2.2; AEC Category: Q200
signal-integrity model Cap
simulation model Cap
footprint 1812_220
footprint 1812_220M
footprint 1812_220L
pins: 1, 2

## 1812GC472KA1
designator C?  ValueDisplayed: 4700pF  (hidden comment: 1812GC472KA1)
CAP, CERM, 4700 pF, 2000 V,+/- 10%, X7R, 1812; Manufacturer: AVX; Polarized: N; CompType: Capacitor; Value: 4700pF; U/M: EA; Cap_F: 0.0000000047; Tolerance_%: 10; VDC_V: 2000; Value2: 2000V; TaMin_C: -55; TaMax_C: 125; Cap_Case: 1812; SizeArea_mm2: 14.4; SizeAreaWB_mm2: 23.1; SizeX_mm: 4.5; SizeY_mm: 3.2; SizeZ_mm: 1.35; AEC Category: Q200
signal-integrity model Cap
simulation model Cap
footprint 1812
footprint 1812M
footprint 1812L
footprint 1812_HV
pins: 1, 2

## 1812GC472KAT1A
designator C?  ValueDisplayed: 4700pF  (hidden comment: 1812GC472KAT1A)
CAP, CERM, 4700 pF, 2000 V,+/- 10%, X7R, 1812; Manufacturer: AVX; Polarized: N; CompType: Capacitor; Value: 4700pF; U/M: EA; Cap_F: 0.0000000047; Tolerance_%: 10; VDC_V: 2000; Value2: 2000V; TaMin_C: -55; TaMax_C: 125; Cap_Case: 1812; SizeArea_mm2: 14.4; SizeAreaWB_mm2: 23.1; SizeX_mm: 4.5; SizeY_mm: 3.2; SizeZ_mm: 2.54; AEC Category: Q200; Green_Lifecycle: Active; Green_REACh: Passed
signal-integrity model Cap
simulation model Cap
footprint 1812_254
pins: 1, 2

## 1812HC222KAT1A
designator C?  ValueDisplayed: 2200pF  (hidden comment: 1812HC222KAT1A)
CAP, CERM, 2200 pF, 3000 V,+/- 10%, X7R, 1812; Manufacturer: AVX; Polarized: N; CompType: Capacitor; Value: 2200pF; U/M: EA; Cap_F: 0.0000000022; Tolerance_%: 10; VDC_V: 3000; Value2: 3000V; TaMin_C: -55; TaMax_C: 125; Cap_Case: 1812; SizeArea_mm2: 14.4; SizeAreaWB_mm2: 23.1; SizeX_mm: 4.5; SizeY_mm: 3.2; SizeZ_mm: 2.54; AEC Category: Q200
signal-integrity model Cap
simulation model Cap
footprint 1812_254
pins: 1, 2

## 1812SC103KAT1A
designator C?  ValueDisplayed: 0.01µF  (hidden comment: 1812SC103KAT1A)
CAP, CERM, 0.01 µF, 1500 V,+/- 10%, X7R, 1812; Manufacturer: AVX; Polarized: N; CompType: Capacitor; Value: 0.01uF; U/M: EA; Cap_F: 0.00000001; Tolerance_%: 10; ESR_ohm: 0.05; Value1: 0.05 ohm; VDC_V: 1500; Value2: 1500V; TaMin_C: -55; TaMax_C: 125; Cap_Case: 1812; SizeArea_mm2: 14.4; SizeAreaWB_mm2: 23.1; SizeX_mm: 4.5; SizeY_mm: 3.2; SizeZ_mm: 1.35; AEC Category: Q200; Green_Lifecycle: Not Set; Green_REACh: Incomplete
signal-integrity model Cap
simulation model Cap
footprint 1812
footprint 1812M
footprint 1812L
footprint 1812_HV
pins: 1, 2

## 1812Y5000474KXTWS2
designator C?  ValueDisplayed: 0.47µF  (hidden comment: 1812Y5000474KXTWS2)
CAP, CERM, 0.47 µF, 500 V,+/- 10%, X7R, 1812; Manufacturer: Knowles Capacitors; Polarized: N; CompType: Capacitor; Value: 0.47uF; U/M: EA; Cap_F: 0.00000047; Tolerance_%: 10; VDC_V: 500; Value2: 500V; TaMin_C: -55; TaMax_C: 125; Cap_Case: 1812; SizeArea_mm2: 14.4; SizeAreaWB_mm2: 23.1; SizeX_mm: 4.5; SizeY_mm: 3.2; SizeZ_mm: 2.54; AEC Category: Q200; Green_Lifecycle: Not Set; Green_REACh: Incomplete
signal-integrity model Cap
simulation model Cap
footprint 1812_254
pins: 1, 2

## 1825GC103KA11A
designator C?  ValueDisplayed: 0.01µF  (hidden comment: 1825GC103KA11A)
CAP, CERM, 0.01 µF, 2000 V,+/- 10%, X7R, 1825; Manufacturer: AVX; Polarized: N; CompType: Capacitor; Value: 0.01uF; U/M: EA; Cap_F: 0.00000001; Tolerance_%: 10; VDC_V: 2000; Value2: 2000V; TaMin_C: -55; TaMax_C: 125; Cap_Case: 1825; SizeArea_mm2: 28.8; SizeAreaWB_mm2: 54.6; SizeX_mm: 4.5; SizeY_mm: 6.4; SizeZ_mm: 2.54; AEC Category: Q200
signal-integrity model Cap
simulation model Cap
footprint 1825_254
pins: 1, 2

## 1825GC103KAT1A
designator C?  ValueDisplayed: 0.01µF  (hidden comment: 1825GC103KAT1A)
CAP, CERM, 0.01 µF, 2000 V,+/- 10%, X7R, 1825; Manufacturer: AVX; Polarized: N; CompType: Capacitor; Value: 0.01uF; U/M: EA; Cap_F: 0.00000001; Tolerance_%: 10; VDC_V: 2000; Value2: 2000V; TaMin_C: -55; TaMax_C: 125; Cap_Case: 1825; SizeArea_mm2: 28.8; SizeAreaWB_mm2: 54.6; SizeX_mm: 4.5; SizeY_mm: 6.4; SizeZ_mm: 1.1; AEC Category: Q200
signal-integrity model Cap
simulation model Cap
footprint 1825
footprint 1825_M
footprint 1825_L
pins: 1, 2

## 1825PC105KAT1A
designator C?  ValueDisplayed: 1µF  (hidden comment: 1825PC105KAT1A)
CAP, CERM, 1 µF, 250 V,+/- 10%, X7R, 1825; Manufacturer: AVX; Polarized: N; CompType: Capacitor; Value: 1uF; U/M: EA; Cap_F: 0.000001; Tolerance_%: 10; VDC_V: 250; Value2: 250V; TaMin_C: -55; TaMax_C: 125; Cap_Case: 1825; SizeArea_mm2: 28.8; SizeAreaWB_mm2: 54.6; SizeX_mm: 4.5; SizeY_mm: 6.4; SizeZ_mm: 2.54; AEC Category: Q200
signal-integrity model Cap
simulation model Cap
footprint 1825_254
pins: 1, 2

## 1825SC183MAT3A
designator C?  ValueDisplayed: 0.018µF  (hidden comment: 1825SC183MAT3A)
CAP, CERM, 0.018 µF, 1500 V,+/- 20%, X7R, 1825; Manufacturer: AVX; Polarized: N; CompType: Capacitor; Value: 0.018uF; U/M: EA; Cap_F: 0.000000018; Tolerance_%: 20; VDC_V: 1500; Value2: 1500V; TaMin_C: -55; TaMax_C: 125; Cap_Case: 1825; SizeArea_mm2: 28.8; SizeAreaWB_mm2: 54.6; SizeX_mm: 4.5; SizeY_mm: 6.4; SizeZ_mm: 2.54; AEC Category: Q200
signal-integrity model Cap
simulation model Cap
footprint 1825_254
pins: 1, 2

## 2220Y6300105KXTWS2
designator C?  ValueDisplayed: 1µF  (hidden comment: 2220Y6300105KXTWS2)
CAP, CERM, 1 µF, 630 V,+/- 10%, X7R, AEC-Q200 Grade 1, 2220; Manufacturer: Knowles Capacitors; Polarized: N; CompType: Capacitor; Value: 1uF; U/M: EA; Cap_F: 0.000001; Tolerance_%: 10; VDC_V: 630; Value2: 630V; TaMin_C: -55; TaMax_C: 125; Cap_Case: 2220; SizeArea_mm2: 28.5; SizeAreaWB_mm2: 53.9; SizeX_mm: 5.7; SizeY_mm: 5; SizeZ_mm: 4.5; AEC Category: Q200; AEC Qualified: Y; AEC Grade: 1
signal-integrity model Cap
simulation model Cap
footprint 2220_450
pins: 1, 2

## 2225PC125MAT1A
designator C?  ValueDisplayed: 1.2µF  (hidden comment: 2225PC125MAT1A)
CAP, CERM, 1.2 µF, 250 V,+/- 20%, X7R, 2225; Manufacturer: AVX; Polarized: N; CompType: Capacitor; Value: 1.2uF; U/M: EA; Cap_F: 0.0000012; Tolerance_%: 20; VDC_V: 250; Value2: 250V; TaMin_C: -55; TaMax_C: 125; Cap_Case: 2225; SizeArea_mm2: 35.91; SizeAreaWB_mm2: 63.91; SizeX_mm: 5.7; SizeY_mm: 6.3; SizeZ_mm: 2; AEC Category: Q200; Green_Lifecycle: Not Set; Green_REACh: Incomplete
signal-integrity model Cap
simulation model Cap
footprint 2225
footprint 2225_M
footprint 2225_L
pins: 1, 2

## 3640KA120KAT3A
designator C?  ValueDisplayed: 12pF  (hidden comment: 3640KA120KAT3A)
CAP, CERM, 12 pF, 5000 V,+/- 10%, C0G/NP0, Chip Capacitor, 2-Leads, Body 9.39x10.45mm; Manufacturer: AVX; Polarized: N; Value: 12pF; U/M: EA; Cap_F: 0.000000000012; Tolerance_%: 10; VDC_V: 5000; Value2: 5000V; TaMin_C: -55; TaMax_C: 125; Cap_Case: 3640; SizeArea_mm2: 93.228; SizeAreaWB_mm2: 135.908; SizeX_mm: 9.14; SizeY_mm: 10.2; SizeZ_mm: 2.54; AEC Category: Q200
signal-integrity model Cap
simulation model Cap
footprint 3640_N
footprint 3640_M
footprint 3640_L
pins: 1, 2

## 04025A101FAT2A
designator C?  ValueDisplayed: 100pF  (hidden comment: 04025A101FAT2A)
CAP, CERM, 100 pF, 50 V,+/- 1%, C0G/NP0, 0402; Manufacturer: AVX; Polarized: N; CompType: Capacitor; Value: 100pF; U/M: EA; Cap_F: 0.0000000001; Tolerance_%: 1; VDC_V: 50; Value2: 50V; TaMin_C: -55; TaMax_C: 125; Cap_Case: 0402; SizeArea_mm2: 0.5; SizeAreaWB_mm2: 3; SizeZ_mm: 0.6; AEC Category: Q200; Green_Lifecycle: Active; Green_REACh: Passed
signal-integrity model Cap
simulation model Cap
footprint 0402
footprint 0402M
footprint 0402L
footprint 0402S
pins: 1, 2

## 04025A181FAT2A
designator C?  ValueDisplayed: 180pF  (hidden comment: 04025A181FAT2A)
CAP, CERM, 180 pF, 50 V,+/- 1%, C0G/NP0, 0402; Manufacturer: AVX; Polarized: N; CompType: Capacitor; Value: 180pF; U/M: EA; Cap_F: 0.00000000018; Tolerance_%: 1; VDC_V: 50; Value2: 50V; TaMin_C: -55; TaMax_C: 125; Cap_Case: 0402; SizeArea_mm2: 0.5; SizeAreaWB_mm2: 3; SizeZ_mm: 0.6; AEC Category: Q200; Green_Lifecycle: Active; Green_REACh: Passed
signal-integrity model Cap
simulation model Cap
footprint 0402
footprint 0402M
footprint 0402L
footprint 0402S
pins: 1, 2

## 04025C132KAT2A
designator C?  ValueDisplayed: 1300pF  (hidden comment: 04025C132KAT2A)
CAP, CERM, 1300 pF, 50 V,+/- 10%, X7R, 0402; Manufacturer: AVX; Polarized: N; CompType: Capacitor; Value: 1300pF; U/M: EA; Cap_F: 0.0000000013; Tolerance_%: 10; VDC_V: 50; Value2: 50V; TaMin_C: -55; TaMax_C: 125; Cap_Case: 0402; SizeArea_mm2: 0.5; SizeAreaWB_mm2: 3; SizeX_mm: 1; SizeZ_mm: 0.6; AEC Category: Q200; Green_Lifecycle: Not Set; Green_REACh: Incomplete
signal-integrity model Cap
simulation model Cap
footprint 0402
footprint 0402M
footprint 0402L
footprint 0402S
pins: 1, 2

## 04025U100CAT2A
designator C?  ValueDisplayed: 10pF  (hidden comment: 04025U100CAT2A)
CAP, CERM, 10 pF, 50 V,+/- 2.5%, C0G/NP0, AEC-Q200 Grade 1, 0402; Manufacturer: AVX; Polarized: N; CompType: Capacitor; Value: 10pF; U/M: EA; Cap_F: 0.00000000001; Tolerance_%: 2.5; VDC_V: 50; Value2: 50V; TaMin_C: -55; TaMax_C: 125; Cap_Case: 0402; SizeArea_mm2: 0.5; SizeAreaWB_mm2: 3; SizeX_mm: 1; SizeZ_mm: 0.6; AEC Category: Q200; AEC Qualified: Y; Green_Lifecycle: Active; Green_REACh: Passed
signal-integrity model Cap
simulation model Cap
footprint 0402
footprint 0402M
footprint 0402L
footprint 0402S
pins: 1, 2

## 04026D474KAT2A
designator C?  ValueDisplayed: 0.47µF  (hidden comment: 04026D474KAT2A)
CAP, CERM, 0.47 µF, 6.3 V,+/- 10%, X5R, 0402; Manufacturer: AVX; Polarized: N; CompType: Capacitor; Value: 0.47uF; U/M: EA; Cap_F: 0.00000047; Tolerance_%: 10; VDC_V: 6.3; Value2: 6.3V; TaMin_C: -55; TaMax_C: 85; Cap_Case: 0402; SizeArea_mm2: 0.5; SizeAreaWB_mm2: 3; SizeX_mm: 1; SizeZ_mm: 0.6; AEC Category: Q200; Green_Lifecycle: Active; Green_REACh: Passed
signal-integrity model Cap
simulation model Cap
footprint 0402
footprint 0402M
footprint 0402L
footprint 0402S
pins: 1, 2

## 06031A330JAT2A
designator C?  ValueDisplayed: 33pF  (hidden comment: 06031A330JAT2A)
CAP, CERM, 33 pF, 100 V,+/- 5%, C0G/NP0, 0603; Manufacturer: AVX; Polarized: N; CompType: Capacitor; Value: 33pF; U/M: EA; Cap_F: 0.000000000033; Tolerance_%: 5; ESR_ohm: 0.209; Value1: 0.209 ohm; VDC_V: 100; Value2: 100V; TaMin_C: -55; TaMax_C: 125; Cap_Case: 0603; SizeArea_mm2: 1.28; SizeAreaWB_mm2: 4.68; SizeX_mm: 1.6; SizeY_mm: 0.8; SizeZ_mm: 1; AEC Category: Q200; Green_Lifecycle: Active; Green_REACh: Passed
signal-integrity model Cap
simulation model Cap
footprint 0603
footprint 0603M
footprint 0603L
footprint 0603_HV
footprint 0603S
pins: 1, 2

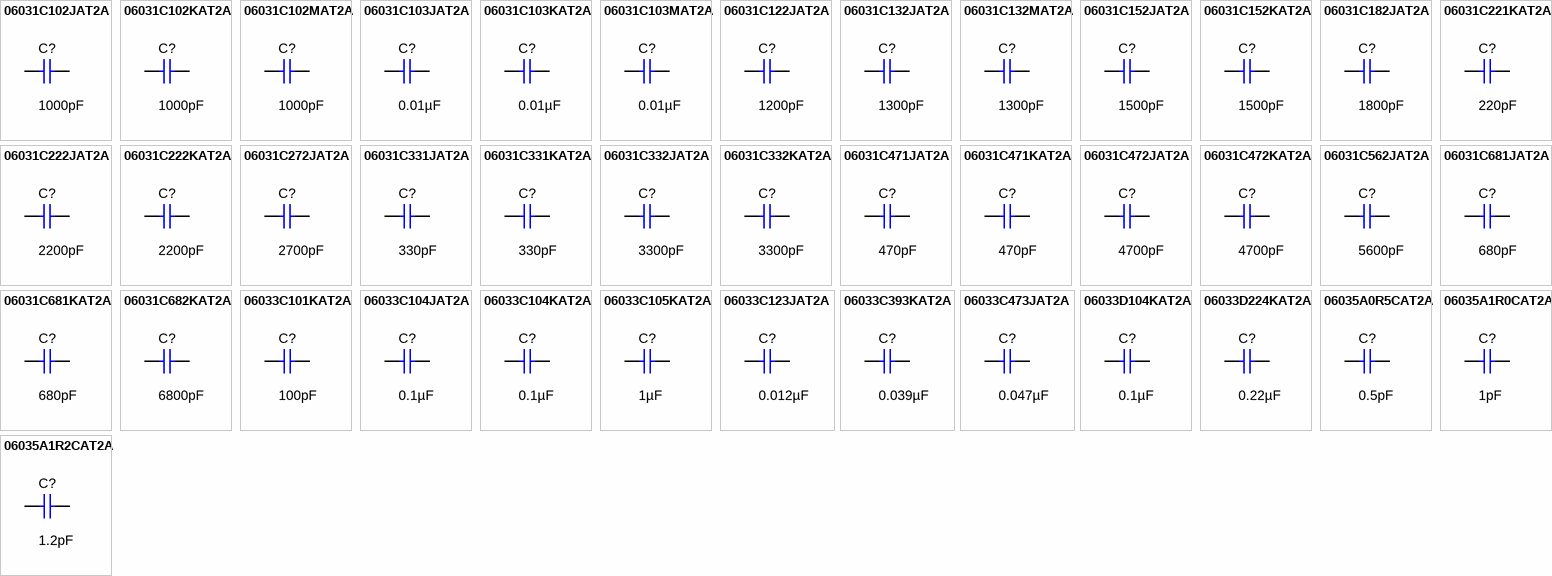
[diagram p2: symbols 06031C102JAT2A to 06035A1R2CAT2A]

## 06031C102JAT2A
designator C?  ValueDisplayed: 1000pF  (hidden comment: 06031C102JAT2A)
CAP, CERM, 1000 pF, 100 V,+/- 5%, X7R, 0603; Manufacturer: AVX; Polarized: N; CompType: Capacitor; Value: 1000pF; U/M: EA; Cap_F: 0.000000001; Tolerance_%: 5; ESR_ohm: 0.276; Value1: 0.276 ohm; VDC_V: 100; Value2: 100V; TaMin_C: -55; TaMax_C: 125; Cap_Case: 0603; SizeArea_mm2: 1.28; SizeAreaWB_mm2: 4.68; SizeX_mm: 1.6; SizeY_mm: 0.8; SizeZ_mm: 1; AEC Category: Q200; Green_Lifecycle: Active; Green_REACh: Passed
signal-integrity model Cap
simulation model Cap
footprint 0603
footprint 0603M
footprint 0603L
footprint 0603_HV
footprint 0603S
pins: 1, 2

## 06031C102KAT2A
designator C?  ValueDisplayed: 1000pF  (hidden comment: 06031C102KAT2A)
CAP, CERM, 1000 pF, 100 V,+/- 10%, X7R, 0603; Manufacturer: AVX; Polarized: N; CompType: Capacitor; Value: 1000pF; U/M: EA; Cap_F: 0.000000001; Tolerance_%: 10; ESR_ohm: 0.276; Value1: 0.276 ohm; VDC_V: 100; Value2: 100V; TaMin_C: -55; TaMax_C: 125; Cap_Case: 0603; SizeArea_mm2: 1.28; SizeAreaWB_mm2: 4.68; SizeX_mm: 1.6; SizeY_mm: 0.8; SizeZ_mm: 1; AEC Category: Q200; Green_Lifecycle: Active; Green_REACh: Passed
signal-integrity model Cap
simulation model Cap
footprint 0603
footprint 0603M
footprint 0603L
footprint 0603_HV
footprint 0603S
pins: 1, 2

## 06031C102MAT2A
designator C?  ValueDisplayed: 1000pF  (hidden comment: 06031C102MAT2A)
CAP, CERM, 1000 pF, 100 V,+/- 20%, X7R, 0603; Manufacturer: AVX; Polarized: N; CompType: Capacitor; Value: 1000pF; U/M: EA; Cap_F: 0.000000001; Tolerance_%: 20; ESR_ohm: 0.276; Value1: 0.276 ohm; VDC_V: 100; Value2: 100V; TaMin_C: -55; TaMax_C: 125; Cap_Case: 0603; SizeArea_mm2: 1.28; SizeAreaWB_mm2: 4.68; SizeX_mm: 1.6; SizeY_mm: 0.8; SizeZ_mm: 1; AEC Category: Q200; Green_Lifecycle: Active; Green_REACh: Passed
signal-integrity model Cap
simulation model Cap
footprint 0603
footprint 0603M
footprint 0603L
footprint 0603_HV
footprint 0603S
pins: 1, 2

## 06031C103JAT2A
designator C?  ValueDisplayed: 0.01µF  (hidden comment: 06031C103JAT2A)
CAP, CERM, 0.01 µF, 100 V,+/- 5%, X7R, 0603; Manufacturer: AVX; Polarized: N; CompType: Capacitor; Value: 0.01uF; U/M: EA; Cap_F: 0.00000001; Tolerance_%: 5; ESR_ohm: 0.098; Value1: 0.098 ohm; VDC_V: 100; Value2: 100V; TaMin_C: -55; TaMax_C: 125; Cap_Case: 0603; SizeArea_mm2: 1.28; SizeAreaWB_mm2: 4.68; SizeX_mm: 1.6; SizeY_mm: 0.8; SizeZ_mm: 1; AEC Category: Q200; Green_Lifecycle: Active; Green_REACh: Passed
signal-integrity model Cap
simulation model Cap
footprint 0603
footprint 0603M
footprint 0603L
footprint 0603_HV
footprint 0603S
pins: 1, 2

## 06031C103KAT2A
designator C?  ValueDisplayed: 0.01µF  (hidden comment: 06031C103KAT2A)
CAP, CERM, 0.01 µF, 100 V,+/- 10%, X7R, 0603; Manufacturer: AVX; Polarized: N; CompType: Capacitor; Value: 0.01uF; U/M: EA; Cap_F: 0.00000001; Tolerance_%: 10; ESR_ohm: 0.098; Value1: 0.098 ohm; VDC_V: 100; Value2: 100V; TaMin_C: -55; TaMax_C: 125; Cap_Case: 0603; SizeArea_mm2: 1.28; SizeAreaWB_mm2: 4.68; SizeX_mm: 1.6; SizeY_mm: 0.8; SizeZ_mm: 1; AEC Category: Q200; Green_Lifecycle: Active; Green_REACh: Passed
signal-integrity model Cap
simulation model Cap
footprint 0603
footprint 0603M
footprint 0603L
footprint 0603_HV
footprint 0603S
pins: 1, 2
